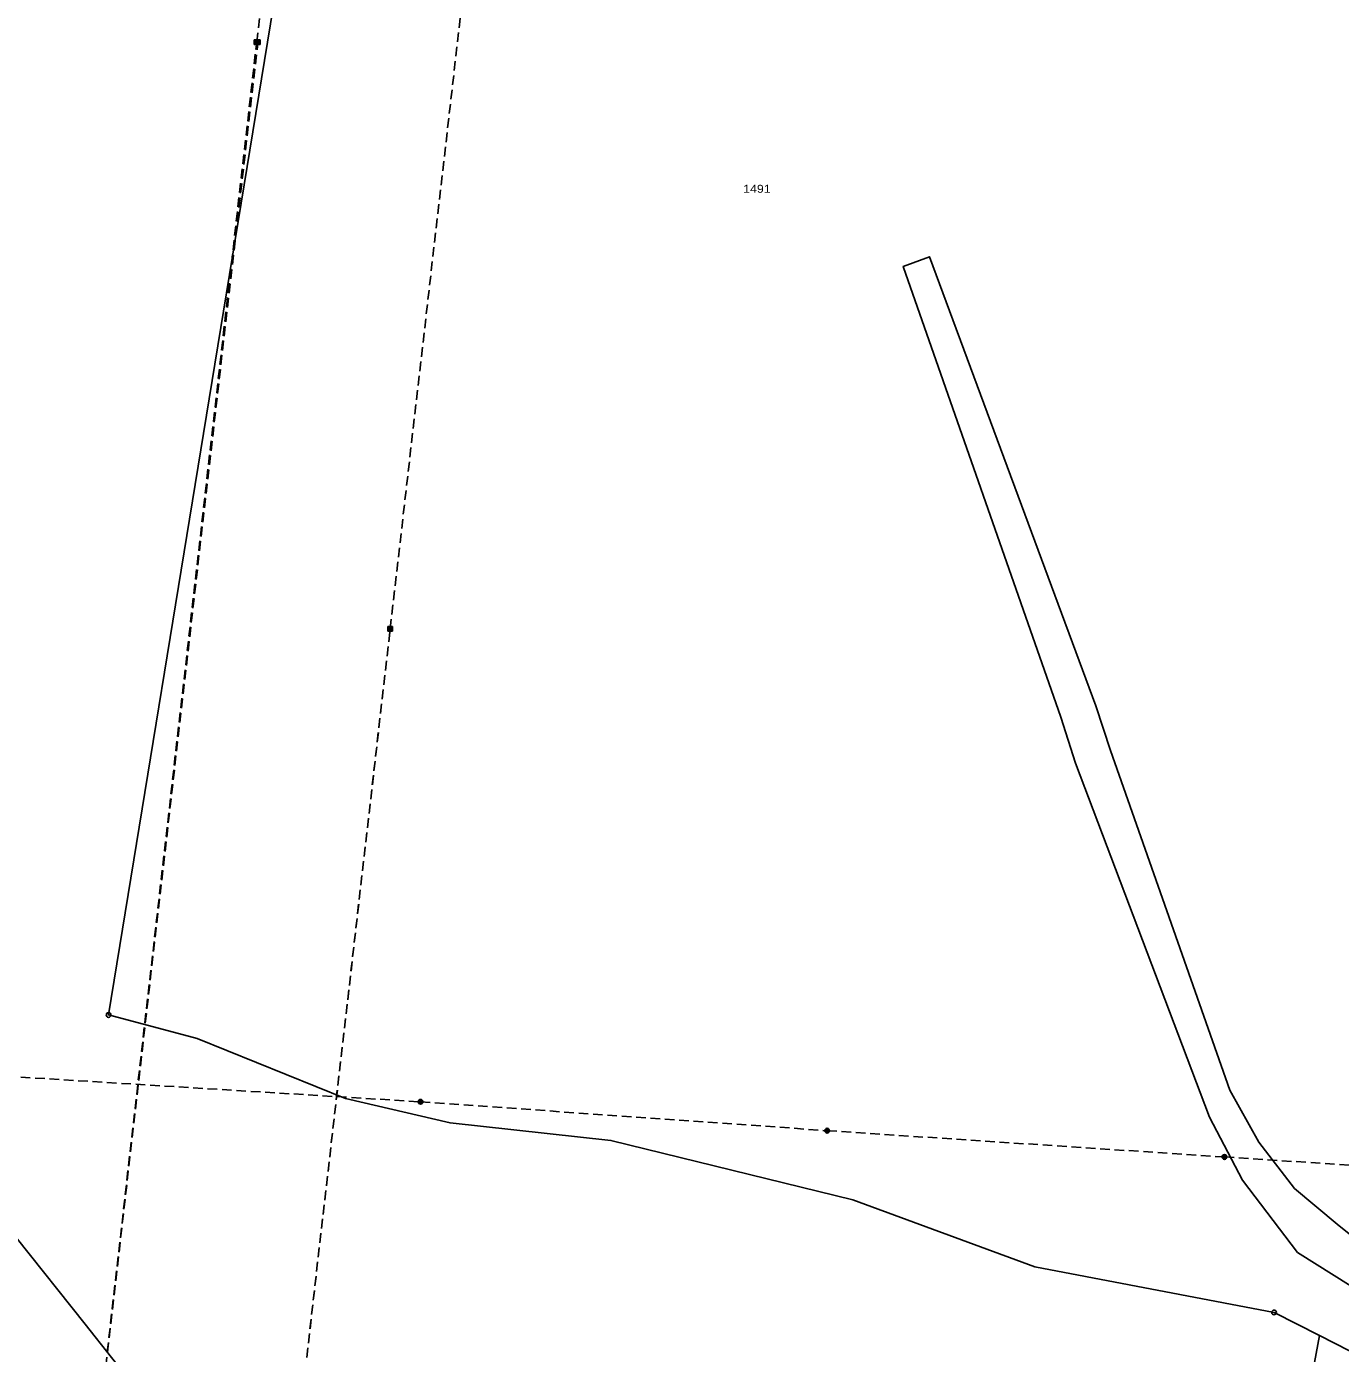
# Model space of a CAD drawing. Extents: x -872229 to -869198, y -1075981 to -1074329.
# Drawn here: x -871865 to -871585.9, y -1075170.8 to -1074889 of the extents above; entities that cross this region are included whole.
import ezdxf

# ---------------------------------------------------------------- set-up
doc = ezdxf.new("R2010")
doc.units = 0
doc.header["$LTSCALE"] = 0.68
doc.linetypes.add('MEDIUM_DASHED', pattern=[4.5, 3, -1.5])
for name, color, linetype, lineweight in [('1', 7, 'Continuous', 25), ('6', 7, 'Continuous', 25), ('8', 7, 'Continuous', 25)]:
    doc.layers.add(name, color=color, linetype=linetype, lineweight=lineweight)
doc.layers.add('2', color=7, linetype='Continuous')

msp = doc.modelspace()

# ---------------------------------------------------------------- linework, layer by layer
at = {"layer": '1'}
for points in [[(-871880.39, -1074773.91), (-871852.19, -1074788.97), (-871835.02, -1074800.17), (-871811.94, -1074817.18), (-871802.66, -1074823.82), (-871825.02, -1074960.68), (-871847.6, -1075098.95), (-871828.77, -1075103.92), (-871797.23, -1075116.69), (-871775.04, -1075121.88), (-871740.88, -1075125.59), (-871689.47, -1075138.24), (-871650.87, -1075152.43), (-871600.02, -1075162.14), (-871590.36, -1075167.06)], [(-871578.94, -1075149.53), (-871586.61, -1075143.41), (-871595.67, -1075135.77), (-871603.22, -1075125.93), (-871609.43, -1075114.89), (-871634.73, -1075042.8), (-871637.87, -1075033.25), (-871673.23, -1074937.88), (-871678.77, -1074939.93), (-871645.3, -1075035.68), (-871642.21, -1075045.44), (-871613.74, -1075120.68), (-871606.71, -1075134.04), (-871595.04, -1075149.42), (-871580.06, -1075158.85)], [(-871852.55, -1075164.62), (-871867.22, -1075146.19), (-871887.9, -1075113.56), (-871891.53, -1075104.31), (-871917.03, -1075102.2)], [(-871829.16, -1075194.06), (-871838.74, -1075182), (-871846.94, -1075171.67), (-871852.55, -1075164.62)], [(-871152.53, -1075228.75), (-871324.15, -1075210.15), (-871498.95, -1075191.88), (-871564.6, -1075180.17), (-871590.36, -1075167.06), (-871608.79, -1075266.42)]]:
    msp.add_lwpolyline(points, dxfattribs=at)
at = {"layer": '6', "linetype": 'MEDIUM_DASHED'}
for p, q in [((-871816.13, -1074892.32), (-871801.92, -1074769.82)), ((-871787.77, -1075016.91), (-871761.64, -1074789.1)), ((-871854.8, -1075231.4), (-871815.86, -1074892.29)), ((-871847.86, -1075170.52), (-871816.13, -1074892.32)), ((-871817.35, -1075275.06), (-871787.76, -1075016.92)), ((-871810.73, -1075217.27), (-871787.77, -1075016.91)), ((-871878.47, -1075111.4), (-871781.31, -1075117.39)), ((-871781.31, -1075117.39), (-871694.96, -1075123.52))]:
    msp.add_line(p, q, dxfattribs=at)
at = {"layer": '6'}
for p, q in [((-871816.632, -1074891.819), (-871815.631, -1074891.819)), ((-871816.632, -1074892.819), (-871816.632, -1074891.819)), ((-871816.632, -1074892.019), (-871815.631, -1074892.019)), ((-871816.632, -1074892.219), (-871815.631, -1074892.219)), ((-871816.431, -1074892.819), (-871816.431, -1074891.819)), ((-871816.362, -1074891.789), (-871815.361, -1074891.789)), ((-871816.362, -1074892.789), (-871816.362, -1074891.789)), ((-871816.362, -1074891.989), (-871815.361, -1074891.989)), ((-871816.362, -1074892.189), (-871815.361, -1074892.189)), ((-871816.232, -1074892.819), (-871816.232, -1074891.819)), ((-871816.161, -1074892.789), (-871816.161, -1074891.789)), ((-871816.031, -1074892.819), (-871816.031, -1074891.819)), ((-871815.962, -1074892.789), (-871815.962, -1074891.789)), ((-871815.832, -1074892.819), (-871815.832, -1074891.819)), ((-871815.761, -1074892.789), (-871815.761, -1074891.789)), ((-871815.631, -1074892.819), (-871815.631, -1074891.819)), ((-871815.562, -1074892.789), (-871815.562, -1074891.789)), ((-871815.361, -1074892.789), (-871815.361, -1074891.789)), ((-871816.632, -1074892.419), (-871815.631, -1074892.419)), ((-871816.632, -1074892.619), (-871815.631, -1074892.619)), ((-871816.632, -1074892.819), (-871815.631, -1074892.819)), ((-871816.362, -1074892.389), (-871815.361, -1074892.389)), ((-871816.362, -1074892.589), (-871815.361, -1074892.589)), ((-871816.362, -1074892.789), (-871815.361, -1074892.789)), ((-871788.272, -1075016.409), (-871787.271, -1075016.409)), ((-871788.272, -1075017.409), (-871788.272, -1075016.409)), ((-871788.272, -1075016.609), (-871787.271, -1075016.609)), ((-871788.272, -1075016.809), (-871787.271, -1075016.809)), ((-871788.272, -1075017.009), (-871787.271, -1075017.009)), ((-871788.272, -1075017.209), (-871787.271, -1075017.209)), ((-871788.272, -1075017.409), (-871787.271, -1075017.409)), ((-871788.262, -1075016.419), (-871787.261, -1075016.419)), ((-871788.262, -1075017.419), (-871788.262, -1075016.419)), ((-871788.262, -1075016.619), (-871787.261, -1075016.619)), ((-871788.262, -1075016.819), (-871787.261, -1075016.819)), ((-871788.262, -1075017.019), (-871787.261, -1075017.019)), ((-871788.262, -1075017.219), (-871787.261, -1075017.219)), ((-871788.262, -1075017.419), (-871787.261, -1075017.419)), ((-871788.071, -1075017.409), (-871788.071, -1075016.409)), ((-871788.061, -1075017.419), (-871788.061, -1075016.419)), ((-871787.872, -1075017.409), (-871787.872, -1075016.409)), ((-871787.862, -1075017.419), (-871787.862, -1075016.419)), ((-871787.671, -1075017.409), (-871787.671, -1075016.409)), ((-871787.661, -1075017.419), (-871787.661, -1075016.419)), ((-871787.472, -1075017.409), (-871787.472, -1075016.409)), ((-871787.462, -1075017.419), (-871787.462, -1075016.419)), ((-871787.271, -1075017.409), (-871787.271, -1075016.409)), ((-871787.261, -1075017.419), (-871787.261, -1075016.419))]:
    msp.add_line(p, q, dxfattribs=at)
at = {"layer": '6', "linetype": 'MEDIUM_DASHED'}
msp.add_lwpolyline([(-871694.96, -1075123.52), (-871610.56, -1075129.11), (-871521.87, -1075134.87)], dxfattribs=at)
at = {"layer": '6'}
for centre, radius in [((-871781.3134, -1075117.3899), 0.5), ((-871781.3134, -1075117.3899), 0.4), ((-871781.3134, -1075117.3899), 0.3), ((-871781.3134, -1075117.3899), 0.2), ((-871781.3134, -1075117.3899), 0.1), ((-871694.9634, -1075123.5199), 0.5), ((-871694.9634, -1075123.5199), 0.4), ((-871694.9634, -1075123.5199), 0.3), ((-871694.9634, -1075123.5199), 0.2), ((-871694.9634, -1075123.5199), 0.1), ((-871610.5634, -1075129.1099), 0.5), ((-871610.5634, -1075129.1099), 0.4), ((-871610.5634, -1075129.1099), 0.3), ((-871610.5634, -1075129.1099), 0.2), ((-871610.5634, -1075129.1099), 0.1)]:
    msp.add_circle(centre, radius, dxfattribs=at)
at = {"layer": '8'}
for centre, radius in [((-871847.6, -1075098.9499), 0.5), ((-871847.6, -1075098.9499), 0.0303), ((-871600.02, -1075162.1399), 0.5), ((-871600.02, -1075162.1399), 0.0303)]:
    msp.add_circle(centre, radius, dxfattribs=at)

# ---------------------------------------------------------------- texts
at = {"layer": '2', "width": 1.15}
msp.add_text('1491', height=1.7, dxfattribs=at).set_placement((-871712.78, -1074924.3))

doc.saveas('drawing.dxf')
